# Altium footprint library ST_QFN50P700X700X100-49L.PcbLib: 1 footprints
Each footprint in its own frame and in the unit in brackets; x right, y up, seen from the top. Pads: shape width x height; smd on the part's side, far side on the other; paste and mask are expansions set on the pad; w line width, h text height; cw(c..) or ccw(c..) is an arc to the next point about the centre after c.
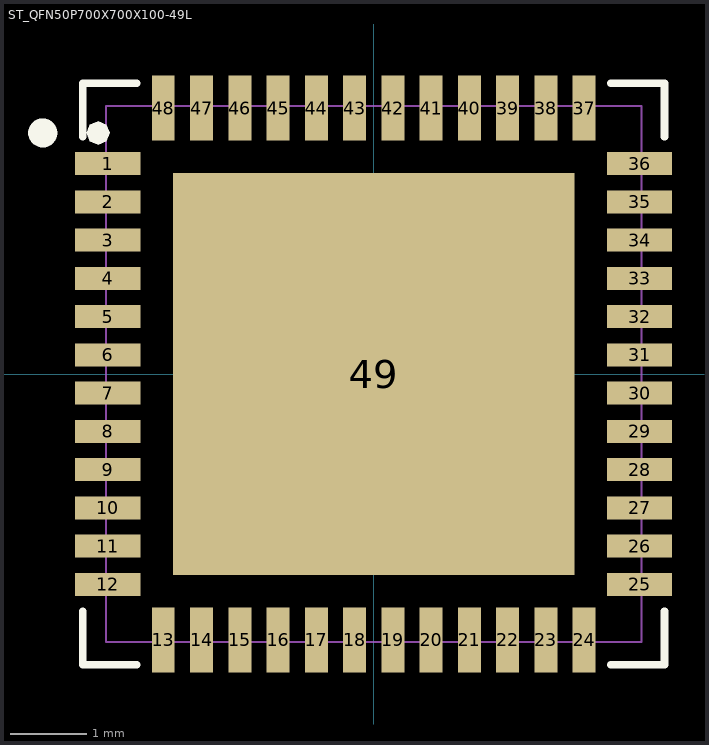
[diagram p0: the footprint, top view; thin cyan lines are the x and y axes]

## ST_QFN50P700X700X100-49L [mm] "ST_QFN50P700X700X100-49L"
pads (49):
  rect 0.85x0.3 smd mask+0.025: 1(-3.475,2.75) 2(-3.475,2.25) 3(-3.475,1.75) 4(-3.475,1.25) 5(-3.475,0.75) 6(-3.475,0.25) 7(-3.475,-0.25) 8(-3.475,-0.75) 9(-3.475,-1.25) 10(-3.475,-1.75) 11(-3.475,-2.25) 12(-3.475,-2.75) 25(3.475,-2.75) 26(3.475,-2.25) 27(3.475,-1.75) 28(3.475,-1.25) 29(3.475,-0.75) 30(3.475,-0.25) 31(3.475,0.25) 32(3.475,0.75) 33(3.475,1.25) 34(3.475,1.75) 35(3.475,2.25) 36(3.475,2.75)
  rect 0.3x0.85 smd mask+0.025: 13(-2.75,-3.475) 14(-2.25,-3.475) 15(-1.75,-3.475) 16(-1.25,-3.475) 17(-0.75,-3.475) 18(-0.25,-3.475) 19(0.25,-3.475) 20(0.75,-3.475) 21(1.25,-3.475) 22(1.75,-3.475) 23(2.25,-3.475) 24(2.75,-3.475) 37(2.75,3.475) 38(2.25,3.475) 39(1.75,3.475) 40(1.25,3.475) 41(0.75,3.475) 42(0.25,3.475) 43(-0.25,3.475) 44(-0.75,3.475) 45(-1.25,3.475) 46(-1.75,3.475) 47(-2.25,3.475) 48(-2.75,3.475)
  rect 5.25x5.25 smd mask+0.05: 49(0,0)
Top Overlay:
  circle w0.2: c-4.325,3.15 r0.09
  pour cut-out: -3.447,3.15 -3.492,3.258 -3.6,3.303 -3.708,3.258 -3.753,3.15 -3.708,3.042 -3.6,2.997 -3.492,3.042
  lines w0.1: -3.8,-3.1 -3.8,-3.8 -3.1,-3.8 ; -3.8,3.1 -3.8,3.8 -3.1,3.8 ; 3.1,-3.8 3.8,-3.8 3.8,-3.1 ; 3.1,3.8 3.8,3.8 3.8,3.1
Mechanical 5:
  text "1" at -4.205,2.65 h0.2
  text "14" at -2.34,-4.275 h0.2
  text "13" at -2.84,-4.275 h0.2
  text "4" at -4.205,1.15 h0.2
  text "47" at -2.39,4.075 h0.2
  text "42" at 0.08,4.075 h0.2
  text "3" at -4.205,1.65 h0.2
  text "26" at 4.085,-2.35 h0.2
  text "25" at 4.085,-2.85 h0.2
  text "12" at -4.365,-2.85 h0.2
  text "11" at -4.365,-2.35 h0.2
  text "10" at -4.365,-1.85 h0.2
  text "9" at -4.205,-1.35 h0.2
  text "8" at -4.205,-0.85 h0.2
  text "6" at -4.205,0.15 h0.2
  text "33" at 4.085,1.15 h0.2
  text "32" at 4.085,0.65 h0.2
  text "30" at 4.085,-0.35 h0.2
  text "29" at 4.085,-0.85 h0.2
  text "28" at 4.085,-1.35 h0.2
  text "27" at 4.085,-1.85 h0.2
  text "5" at -4.205,0.65 h0.2
  text "46" at -1.89,4.075 h0.2
  text "44" at -0.89,4.075 h0.2
  text "34" at 4.085,1.65 h0.2
  text "35" at 4.085,2.15 h0.2
  text "36" at 4.08,2.65 h0.2
  text "37" at 2.61,4.075 h0.2
  text "38" at 2.11,4.075 h0.2
  text "39" at 1.61,4.075 h0.2
  text "40" at 1.11,4.075 h0.2
  text "41" at 0.61,4.075 h0.2
  text "24" at 2.66,-4.275 h0.2
  text "23" at 2.16,-4.275 h0.2
  text "22" at 1.66,-4.275 h0.2
  text "21" at 1.16,-4.275 h0.2
  text "19" at 0.16,-4.275 h0.2
  text "18" at -0.34,-4.275 h0.2
  text "17" at -0.84,-4.275 h0.2
  text "16" at -1.34,-4.275 h0.2
  text "49" at 0.03,2.7 h0.2
  text "2" at -4.205,2.15 h0.2
  text "43" at -0.39,4.075 h0.2
  text "31" at 4.085,0.15 h0.2
  text "20" at 0.66,-4.275 h0.2
  text "15" at -1.84,-4.275 h0.2
  text "7" at -4.205,-0.35 h0.2
  text "45" at -1.39,4.075 h0.2
  text "48" at -2.89,4.075 h0.2
Mechanical 6:
  lines w0.025: -3.5,-3.5 -3.5,3.5 3.5,3.5 3.5,-3.5 -3.5,-3.5
Mechanical 7:
  lines w0.025: -3.5,-3.5 3.5,-3.5 3.5,3.5 -3.5,3.5 -3.5,-3.5
Mechanical 15:
  lines w0.001: -0.5,0 0.5,0 ; 0,-0.5 0,0.5
3D body: height 0.94, standoff -0.94, extent -4.857,4.302 -4.857,4.302
3D body: height 1, standoff 0.02, extent -3.5,-3.5 3.5,3.5
3D body: height 0.94, standoff -0.94, extent -3.5,3.5 -3.5,3.5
